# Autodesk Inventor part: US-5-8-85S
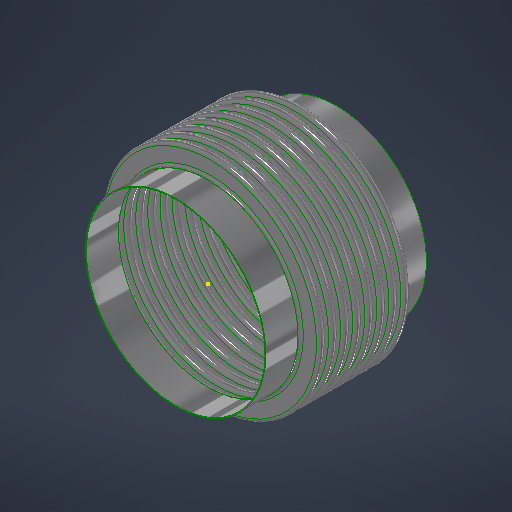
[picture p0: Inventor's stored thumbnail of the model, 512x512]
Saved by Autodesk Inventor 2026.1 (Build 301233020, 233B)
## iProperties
Category: 24 GA (0.024 THICK)
RuleStatus: InUse
Created: 2026-07
Part Number: US-5-8-85S
Project: =STOCK BELLOWS: <Stock Number><SFILL>
Material: ASTM A240-304
Description: =STOCK BELLOWS: <Stock Number>, <SID_> I.D., <SOD_> O.D., <SPLY_> PLY, <Category>, <SNET_CONS> CONS.<PITCH_><STANGENT_> TANGENT<SFILL>
Document SubType Name: Sheet Metal
Designer: LC
Stock Number: U.S-5-8-85S
Surface Area: 659.127 cm^2
Volume: 56.61 cm^3
Sheet Metal Rule: Default
Appearance: STAINLESS STEEL
NET_TUBE: 3.428
COUNTER: 1.500
PBAR: 1.214
PSET: 5.356
PLY: 2
CONS: 2
THK: 0.036
ID: 4.500
OD: 5.500
CONS_: 2
TANGENT: 0.500
PITCH: 0.375
BELLOWS_UPSET: 0.000
NET_CONS: 2
S_CONS: 0
Description_Units: 0
ID_M: 114.30 mm
OD_M: 139.70 mm
THK_M: 0.91 mm
ID_U: 4.500 in
OD_U: 5.500 in
THK_U: 0.036 in
TANGENT2: 0.500
d79: 1.000
d82: 1.000
d83: 26.000
d84: 24.000
d80: 2.571
d81: 10
SID: 2.375
SCONS_: 8
SPITCH: 0.250
SBELLOWS_UPSET: 0.000
SNET_CONS: 8
SS_CONS: 0
SCONS: 8
d174: 8
d177: 0.018
d178: 2.375
d179: 3.000
d180: 0.375
d181: 1.000
d182: 0.000
d190: 8
d191: 1
d192: 1
d193: 8
d194: 0
PART_NUMBER: U.S-5-8-85S
PRESSURE: 85
SIZE: 5.00
STANGENT_: 1.000
d214: 8
d217: 0.030
d218: 6.625
d219: 8.125
d220: 0.500
d221: 1.000
d222: 0.000
d230: 8
d231: 1
d232: 1
d233: 8
d234: 0
STANGENT: 4.000
SPLY_: 1
STHK_: 0.024
SID_: 5.563
SOD_: 6.813
SPITCH_: 0.375
STANGENT__: 1.000
SBELLOWS_UPSET_: 0.000
SDIFF_TAN: 1.000
TAN_TO_TAN: 0.750 in
d252: 2
d275: 2
d287: 0.050
d289: 0.500
d290: 0.000
d263: 2
d265: 1
d268: 2
d269: 0
d286: 2
d288: 1
d291: 2
d292: 0
SOD_NECK: 5 5/8
CFILL: .
SFILL: .
PITCH_: =, <SPITCH_> PITCH,
SREROLL: 0.750
MATTABLE: 20 GA (0.036 THICK)
MESH: ,
CSECT: 2
Author: LC
Keywords: 20 GA (0.036 THICK)
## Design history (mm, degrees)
sketch "Sketch2"
  geometry: L1 (0, -183.595)-(0, 600.956) reference; L2 (58.979, 0)-(57.15, 0); L3 (60.446, -1.467)-(66.554, -1.467); L4 (60.446, -3.296)-(66.554, -3.296); L5 (66.554, -8.058)-(60.446, -8.058); L6 (66.554, -6.229)-(60.446, -6.229); L7 (58.979, -9.525)-(57.15, -9.525); L8 (60.446, 0)-(60.446, -9.525); L9 (66.554, -4.762)-(69.85, -4.763); L10 (57.15, 0)-(57.15, -9.525); L11 (20.376, 102.841)-(20.376, 101.926); L12 (58.262, 488.877)-(58.262, 349.177); L13 (58.262, 479.352)-(58.262, 339.652); L14 (93.133, -58.817)-(93.133, -71.517); L15 (118.746, -66.401)-(118.746, -66.401); L16 (66.554, -6.229)-(66.554, -8.058); L17 (60.446, -6.229)-(60.446, -8.058); L18 (60.446, -7.144)-(66.554, -7.144); L19 (69.85, 0)-(69.85, -9.525); L20 (-66.554, -6.229)-(-66.554, -8.058); L21 (-66.554, -1.467)-(-60.446, -1.467); L22 (-66.554, -3.296)-(-60.446, -3.296); L23 (-60.446, -6.229)-(-66.554, -6.229); L24 (-66.554, -7.144)-(-60.446, -7.144); L25 (-60.446, -8.058)-(-66.554, -8.058); L26 (-60.446, -6.229)-(-60.446, -8.058); L27 (-57.15, -2.522)-(-57.15, -12.047); L28 (-60.446, -4.763)-(-57.15, -4.763); L29 (-66.554, 3.828)-(-66.554, -9.525); L30 (-68.021, 0)-(-69.85, 0); L31 (-69.85, 0)-(-69.85, -9.525); L32 (-68.021, -9.525)-(-69.85, -9.525); A1 r 1.467 centre (60.446, 0) between (58.979, 0) and (60.446, -1.467); A2 r 3.296 centre (60.446, 0) between (57.15, 0) and (60.446, -3.296); A3 r 3.296 centre (66.554, -4.762) between (66.554, -8.058) and (66.554, -1.467); A4 r 1.467 centre (66.554, -4.762) between (66.554, -6.229) and (66.554, -3.296); A5 r 1.467 centre (60.446, -9.525) between (60.446, -8.058) and (58.979, -9.525); A6 r 3.296 centre (60.446, -9.525) between (60.446, -6.229) and (57.15, -9.525); A7 r 2.381 centre (66.554, -4.762) between (66.554, -7.144) and (68.936, -4.762); A8 r 2.381 centre (60.446, -9.525) between (60.446, -7.144) and (58.064, -9.525); A9 r 1.467 centre (-66.554, -9.525) between (-66.554, -8.058) and (-68.021, -9.525); A10 r 1.467 centre (-60.446, -4.763) between (-60.446, -6.229) and (-60.446, -3.296); A11 r 2.381 centre (-60.446, -4.763) between (-60.446, -7.144) and (-58.064, -4.763); A12 r 3.296 centre (-60.446, -4.763) between (-60.446, -8.058) and (-60.446, -1.467); A13 r 2.381 centre (-66.554, -9.525) between (-66.554, -7.144) and (-68.936, -9.525); A14 r 3.296 centre (-66.554, -9.525) between (-66.554, -6.229) and (-69.85, -9.525); A15 r 1.467 centre (-66.554, 0) between (-68.021, 0) and (-66.554, -1.467); A16 r 3.296 centre (-66.554, 0) between (-69.85, 0) and (-66.554, -3.296); 10 further points
  constraints: 62 end point, 38 point on circle, 20 tangent, 16 centre point, 12 parallel, 9 midpoint, 7 vertical, 6 coincident, 6 concentric, 6 point on line, 4 equal radius, 4 perpendicular, 3 horizontal, 1 collinear, 1 horizontal alignment, 10 other
  dimensions: "THK" = 0.9144 distance of L11.start L11.end; "ID" = 114.3 distance of L11.end point (20.376, -12.374); "OD" = 139.7 distance of L12.start L12.end; "PITCH" = 9.525 distance of L12.start L13.start; "TANGENT" = 12.7 distance of L14.start L14.end; "BELLOWS_UPSET" = 0 distance of L15.start L15.end; "d43" = 114.3 diameter of L10 L1 (= ID); "d44" = 139.7 diameter of L9.end L1 (= OD); "d45" = 1.8288 distance between parallel lines of L5 L6 (computed from THK, PLY); "d46" = 3.29565 radius of A3 (computed from PITCH, THK, PLY); "UPSET_PITCH" = 9.525 distance of L2.end L7.end (derived); "SIDEWALL_ANGLE" = 0 deg angle of L3 L9 (derived); "CON_GAP" = 2.9337 distance of point (60.446, -6.229) point (60.446, -3.296) (derived); "TAN1" = 3.74046 dimension on A8 (derived); "TAN2" = 3.74046 dimension on A7 (derived); "LEG1" = 6.1087 distance of L18.start L18.end (derived); "d278" = 1.8288 distance between parallel lines of L25 L23 (derived); "d279" = 3.29565 radius of A12 (derived); "d280" = 9.525 distance of L30.end L31.end (derived); "d281" = 360 deg dimension on L21 L28 (derived); "d282" = 2.9337 distance of point (-66.554, -6.229) point (-66.554, -3.296) (derived); "d283" = 3.74046 dimension on A13 (derived); "d284" = 3.74046 dimension on A11 (derived); "d285" = 6.1087 distance of L24.start L24.end (derived); "d293" = 114.3 diameter of L27 L1 (derived); "d294" = 139.7 diameter of L31 L1 (derived)
  node "Sketch Rectangular Pattern1" dims "d31" = 25.4, "ID" = 114.3
  node "Sketch Rectangular Pattern2" dims "d39" = 25.4, "PITCH" = 9.525
revolve "CONS" stored, may be unused: angle "d48" = 90 deg
node "BELLOW MIDPLANE"
pattern_linear "Rectangular Pattern2" dims "d52" = 9.525 (= UPSET_PITCH)
sketch "Sketch5"
  geometry: C1 r 58.979 at (0, 0) reference; C2 r 57.15 at (0, 0) reference
extrude "TANGENT" new body sketch "Sketch5" distance "d53" = 12.7 (= TANGENT); taper "d54" = 0 deg
revolve "SAMETAN" stored, may be unused: angle "d65" = 90 deg
revolve "DIFFTAN" stored, may be unused: angle "d70" = 90 deg
sketch "Sketch9"
  geometry: L1 (58.391, 0)-(-58.391, 0) reference; L2 (0, -17.78)-(0, 17.78) reference; L3 (41.708, 0)-(-41.708, 0); L4 (41.708, -11.906)-(41.708, 11.906); L5 (29.008, -11.906)-(29.008, 11.906); L6 (15.418, 11.906)-(15.418, -11.906); L7 (-29.008, -11.906)-(-29.008, 11.906); L8 (-41.708, -11.906)-(-41.708, 11.906); L9 (40.914, -11.906)-(40.914, 11.906); L10 (41.708, -11.906)-(40.914, -11.906); L11 (41.708, 11.906)-(40.914, 11.906); L12 (15.815, 11.906)-(15.022, 11.906); L13 (15.022, 11.906)-(15.022, -11.906); L14 (15.022, -11.906)-(15.815, -11.906); L15 (15.815, -11.906)-(15.815, 11.906); L16 (-15.815, 11.906)-(-15.815, -11.906); L17 (-15.418, 11.906)-(-15.418, -11.906); L18 (-15.815, -11.906)-(-15.022, -11.906); L19 (-15.022, -11.906)-(-15.022, 11.906); L20 (-15.022, 11.906)-(-15.815, 11.906); L21 (-41.708, -11.906)-(-40.914, -11.906); L22 (-40.914, -11.906)-(-40.914, 11.906); L23 (-40.914, 11.906)-(-41.708, 11.906); L24 (-41.708, 11.906)-(-41.708, -11.906); L25 (41.708, -0.397)-(-41.708, -0.397); L26 (-41.708, -0.397)-(-41.708, 0.397); L27 (-41.708, 0.397)-(41.708, 0.397); L28 (41.708, 0.397)-(41.708, -0.397); L29 (-41.708, 11.906)-(41.708, 11.906); L30 (41.708, 11.906)-(41.708, 12.7); L31 (41.708, 12.7)-(-41.708, 12.7); L32 (-41.708, 12.7)-(-41.708, 11.906); L33 (41.708, -11.906)-(-41.708, -11.906); L34 (-41.708, -11.906)-(-41.708, -12.7); L35 (-41.708, -12.7)-(41.708, -12.7); L36 (41.708, -12.7)-(41.708, -11.906); 30 further points
  constraints: 68 end point, 13 midpoint, 13 parallel, 8 horizontal, 7 perpendicular, 6 equal length, 3 point on line, 2 vertical, 14 other
  dimensions: "d115" = 23.8125 distance of L4.start L4.end (derived); "d116" = 12.7 distance between parallel lines of L4 L5 (derived); "d117" = 13.58962 distance between parallel lines of L5 L6 (derived); "d125" = 44.42645 distance between parallel lines of L7 L6 (derived); "d127" = 12.7 distance between parallel lines of L8 L7 (derived); "d128" = 26.28962 distance between parallel lines of L6 L4 (derived); "d130" = 83.41607 distance between parallel lines of L8 L4 (derived); "RULER_THK" = 0.79375 distance between parallel lines of L4 L9; "d135" = 0.79375 distance of L13.end L14.end (derived); "d138" = 30.83684 distance of L13.end L16.end (derived); "d143" = 0.79375 distance of L22.end L8.end (derived); "d144" = 0.79375 distance between parallel lines of L27 L25 (derived)
extrude "RULER" join sketch "Sketch9" distance "d149" = 0.79375 (derived); taper "d150" = 0 deg
extrude "BARS" join sketch "Sketch9" distance "d151" = 0.79375 (derived); taper "d152" = 0 deg
pattern_linear "Rectangular Pattern4" dims "d155" = 30.83684 (derived)
sketch "Sketch13"
  geometry: L1 (93.149, -52.467)-(93.149, -77.867); L2 (71.26, 0)-(70.65, 0); L3 (71.26, -9.525)-(70.65, -9.525); L4 (83.839, -7.449)-(73.336, -7.449); L5 (83.839, -6.839)-(73.336, -6.839); L6 (83.839, -4.763)-(86.525, -4.763); L7 (73.336, -2.076)-(83.839, -2.076); L8 (73.336, 0)-(73.336, -9.525); L9 (70.65, 0)-(70.65, -9.525); L10 (58.254, -341.381)-(58.254, -514.431); L11 (58.254, -350.906)-(58.254, -523.956); L12 (58.254, -369.956)-(58.254, -543.006); L13 (58.254, -379.481)-(58.254, -552.531); L14 (58.254, -389.006)-(58.254, -562.056); L15 (58.254, -398.531)-(58.254, -571.581); L16 (58.254, -408.056)-(58.254, -581.106); L17 (58.254, -360.431)-(58.254, -533.481); L18 (20.376, 102.536)-(20.376, 101.926); L19 (73.336, -2.686)-(83.839, -2.686); L20 (0, -696.234)-(0, 235.664) reference; L21 (-23.752, 0)-(142.514, 0) reference; A1 r 2.076 centre (73.336, 0) between (71.26, 0) and (73.336, -2.076); A2 r 2.076 centre (73.336, -9.525) between (73.336, -7.449) and (71.26, -9.525); A3 r 2.686 centre (73.336, -9.525) between (73.336, -6.839) and (70.65, -9.525); A4 r 2.076 centre (83.839, -4.763) between (83.839, -6.839) and (83.839, -2.686); A5 r 2.686 centre (83.839, -4.763) between (83.839, -7.449) and (83.839, -2.076); A6 r 2.686 centre (73.336, 0) between (70.65, 0) and (73.336, -2.686); 6 further points; 1 other entity
  constraints: 38 end point, 15 point on circle, 9 tangent, 6 centre point, 6 parallel, 5 vertical alignment, 4 point on line, 4 vertical, 3 coincident, 3 concentric, 2 collinear, 2 equal radius, 1 horizontal, 1 perpendicular, 23 other
  dimensions: "SBELLOWS_UPSET_" = 0 distance of point (118.762, -66.401) point (118.762, -66.401); "STOTAL_THK_BELLOW__" = 0.6096 distance between parallel lines of L4 L5 (derived); "d224" = 2.68605 radius of A5 (derived); "d225" = 9.525 distance of L2.end L3.end (derived); "SSIDEWALL_ANGLE_" = 0 deg angle of L7 L6 (derived); "SSCON_GAP_" = 4.1529 distance of point (73.336, -6.839) point (73.336, -2.686) (derived); "d235" = 141.3002 diameter of L9 L20 (derived); "d236" = 173.0502 diameter of L6.end L20 (derived)
  node "Sketch Rectangular Pattern4" dims "d228" = 25.4
  node "Sketch Rectangular Pattern5" dims "d229" = 25.4
revolve "SBELLOW" stored, may be unused: angle "d197" = 90 deg
pattern_linear "Rectangular Pattern5" dims "d204" = 9.525 (derived)
revolve "STANGENT" stored, may be unused: angle "d240" = 90 deg
revolve "SSAMETAN" stored, may be unused: angle "d241" = 90 deg
revolve "SDIFFTAN" stored, may be unused: angle "d246" = 90 deg
revolve "INVCON" stored, may be unused: angle "d295" = 90 deg
pattern_linear "Rectangular Pattern6" dims "d298" = 9.525 (derived)
revolve "INVTANGENT" stored, may be unused: angle "d302" = 90 deg
revolve "INVSAMETAN" stored, may be unused: angle "d307" = 90 deg
revolve "INVDIFFTAN" stored, may be unused: angle "d312" = 90 deg
sketch "ID BELLOW MOUNT CALC"
  geometry: L1 (44.45, 0)-(38.1, 0); L2 (38.1, 0)-(38.1, 12.7); L3 (38.1, 12.7)-(44.45, 12.7); L4 (44.45, 12.7)-(44.45, 0); L5 (36.513, 12.7)-(34.684, 12.7); L6 (34.684, 12.7)-(34.684, 0); L7 (34.684, 0)-(36.513, 0); L8 (36.513, 0)-(36.513, 12.7); L9 (0, -2.54)-(0, 15.24) reference; L10 (-8.89, 0)-(53.34, 0) reference; 1 further point
  constraints: 16 end point, 5 parallel, 2 collinear, 2 horizontal, 2 perpendicular
  dimensions: "d314" = 12.7 distance of L5.end L6.end (derived); "d315" = 1.8288 distance of L5.start L5.end (derived); "IG" = 1.5875 distance between parallel lines of L2 L8; "PIPE_OD" = 88.9 diameter of L4 L9; "PIPE_WALL" = 6.35 distance of L2.end L3.end; "ID_MT_BELLOW" = 69.3674 diameter of L6 L9 (derived)
revolve "CFILL" stored, may be unused: angle "d320" = 90 deg
pattern_linear "Rectangular Pattern7" dims "d323" = 9.525 (derived)
revolve "SFILL" stored, may be unused: angle "d324" = 90 deg
pattern_linear "Rectangular Pattern8" dims "d327" = 9.525 (derived)
node "STOCK BELLOW MIDPLANE"
sketch "Sketch21"
  geometry: L1 (0, -100.013)-(0, 100.013) reference; L2 (-100.013, 0)-(100.013, 0) reference; L3 (-0.099, 71.437)-(0.099, 71.437); L4 (0.099, 71.437)-(0.099, 55.562); L5 (0.099, 55.562)-(-0.099, 55.562); L6 (-0.099, 55.562)-(-0.099, 71.437); C1 r 55.562 at (0, 0); C2 r 71.437 at (0, 0); 3 further points
  constraints: 8 end point, 2 centre point, 2 coincident, 2 parallel, 2 tangent, 1 horizontal, 1 perpendicular, 1 other
  dimensions: "d329" = 111.125 diameter of C1 (derived); "d330" = 142.875 diameter of C2 (derived); "d331" = 0.19844 distance of L3.start L3.end
extrude "CLAMSHELL" cut sketch "Sketch21" extent not by distance; stored distance "d332" = 0; taper "d333" = 0 deg
pattern_circular "Circular Pattern1" dims angle "d335" = 180 deg (derived)
node "BELLOW"
sketch "Sketch6"
  geometry: L1 (-19.05, 58.979)-(-6.35, 58.979); L2 (-6.35, 58.979)-(-6.35, 57.15); L3 (-6.35, 57.15)-(-19.05, 57.15); L4 (-19.05, 57.15)-(-19.05, 58.979); L5 (2.54, 0)-(-59.69, 0) reference; L6 (-38.1, -108.388)-(-38.1, 156.601) reference; 1 further point
  constraints: 8 end point, 2 parallel, 1 horizontal, 1 perpendicular
  dimensions: "d61" = 12.7 distance of L2.end L3.end (derived); "d62" = 1.8288 distance of L1.end L2.end (derived); "d63" = 114.3 diameter of L3 L5 (derived); "d64" = 19.05 distance between parallel lines of L4 L6 (derived)
sketch "Sketch12"
  geometry: 1 further point
sketch "Sketch14"
  geometry: L1 (-25.4, 71.26)-(0, 71.26); L2 (0, 71.26)-(0, 70.65); L3 (0, 70.65)-(-25.4, 70.65); L4 (-25.4, 70.65)-(-25.4, 71.26); L5 (5.08, 0)-(-30.48, 0) reference; L6 (0, -11.552)-(0, 69.312) reference; 1 further point
  constraints: 8 end point, 2 parallel, 1 collinear, 1 horizontal, 1 perpendicular
  dimensions: "d237" = 0.6096 distance of L3.end L1.start (derived); "d238" = 141.3002 diameter of L3 L5 (derived); "d239" = 25.4 distance of L1.start L1.end (derived); "SOD_NECK" = 142.5194 diameter of L1 L5 (derived)
sketch "Sketch15"
  geometry: L1 (-11.552, 0)-(69.312, 0) reference; L2 (70.65, -76.2)-(71.26, -76.2); L3 (71.26, -76.2)-(71.26, -101.6); L4 (71.26, -101.6)-(70.65, -101.6); L5 (70.65, -101.6)-(70.65, -76.2); L6 (0, -124.46)-(0, 35.56) reference; 1 further point
  constraints: 8 end point, 2 parallel, 1 horizontal, 1 perpendicular
  dimensions: "d205" = 25.4 distance of L4.end L2.start (derived); "d206" = 0.6096 distance of L3.end L4.end (derived); "d207" = 141.3002 diameter of L5 L6 (derived); "d208" = 76.2 distance between parallel lines of L1 L2 (derived)
node "TANGENT_"
node "SAME_TAN"
sketch "Sketch8"
  geometry: L1 (58.979, -19.05)-(57.15, -19.05); L2 (57.15, -19.05)-(57.15, -31.75); L3 (57.15, -31.75)-(58.979, -31.75); L4 (58.979, -31.75)-(58.979, -19.05); L5 (0, -40.64)-(0, 21.59) reference; L6 (-108.388, 0)-(156.601, 0) reference; 1 further point
  constraints: 8 end point, 2 parallel, 1 horizontal, 1 perpendicular
  dimensions: "d66" = 114.3 diameter of L2 L5 (derived); "TOTAL_THK_BELLOW" = 1.8288 distance of L2.end L3.end (derived); "d68" = 19.05 distance between parallel lines of L1 L6 (derived); "d69" = 12.7 distance of L1.end L2.end (derived)
node "DIFF_TAN"
node "Sketch Rectangular Pattern3" dims "d138" = 30.83684 (derived), "d141" = 25.4
node "SBELLOW_"
node "STANGENT_"
node "SSAME_TAN"
sketch "Sketch16"
  geometry: L1 (71.26, -76.2)-(70.65, -76.2); L2 (70.65, -76.2)-(70.65, -101.6); L3 (70.65, -101.6)-(71.26, -101.6); L4 (71.26, -101.6)-(71.26, -76.2); L5 (0, -124.46)-(0, 35.56) reference; L6 (-11.552, 0)-(69.312, 0) reference; 1 further point
  constraints: 8 end point, 2 parallel, 1 horizontal, 1 perpendicular
  dimensions: "SDIFF_TAN" = 25.4 distance of L3.end L1.start; "d243" = 0.6096 distance of L2.end L3.end (derived); "d244" = 76.2 distance between parallel lines of L1 L6 (derived); "d245" = 141.3002 diameter of L2 L5 (derived)
node "SDIFF_TAN"
body "Solid15"
sketch "Sketch17"
  geometry: L1 (69.85, 12.7)-(68.021, 12.7); L2 (68.021, 12.7)-(68.021, 0); L3 (68.021, 0)-(69.85, 0); L4 (69.85, 0)-(69.85, 12.7); L5 (0, -2.54)-(0, 15.24) reference; L6 (-13.97, 0)-(83.82, 0) reference; 2 further points
  constraints: 8 end point, 2 parallel, 1 horizontal, 1 midpoint, 1 perpendicular, 1 point on line
  dimensions: "INVTANGENT" = 12.7 distance of L3.end L1.start (derived); "d300" = 1.8288 distance of L1.start L1.end (derived); "d301" = 139.7 diameter of L4 L5 (derived)
body "Solid16"
sketch "Sketch18"
  geometry: L1 (69.85, -19.05)-(68.021, -19.05); L2 (68.021, -19.05)-(68.021, -31.75); L3 (68.021, -31.75)-(69.85, -31.75); L4 (69.85, -31.75)-(69.85, -19.05); L5 (-13.97, 0)-(83.82, 0) reference; L6 (0, -40.64)-(0, 21.59) reference; 1 further point
  constraints: 8 end point, 2 parallel, 1 horizontal, 1 perpendicular
  dimensions: "d303" = 19.05 distance between parallel lines of L1 L5 (derived); "d304" = 12.7 distance of L3.end L1.start (derived); "d305" = 1.8288 distance of L2.end L3.end (derived); "d306" = 139.7 diameter of L4 L6 (derived)
body "Solid17"
sketch "Sketch19"
  geometry: L1 (69.85, -19.05)-(68.021, -19.05); L2 (68.021, -19.05)-(68.021, -31.75); L3 (68.021, -31.75)-(69.85, -31.75); L4 (69.85, -31.75)-(69.85, -19.05); L5 (0, -40.64)-(0, 21.59) reference; L6 (-13.97, 0)-(83.82, 0) reference; 1 further point
  constraints: 8 end point, 2 parallel, 1 horizontal, 1 perpendicular
  dimensions: "d308" = 12.7 distance of L1.end L2.end (derived); "d309" = 139.7 diameter of L4 L5 (derived); "d310" = 1.8288 distance of L2.end L3.end (derived); "d311" = 19.05 distance between parallel lines of L1 L6 (derived)
body "Solid18"
body "Solid19"
body "Solid20"
other parameters: "BMPL" = -38.1, "PSET" = 136.0424 (computed from OD, THK, PLY) [user parameter], "PBAR" = 30.83684 (= 0.570796 x PITCH + OD - ID) [user parameter; used in 1 equation term], "COUNTER" = 15 [user parameter], "NET_TUBE" = 87.07367 (computed from CONS_, PBAR, TANGENT) [user parameter], "S_CONS" = 0 [user parameter; used in 1 equation term], "ID_M" = 114.3 (= ID) [user parameter], "OD_M" = 139.7 (= OD) [user parameter], "THK_M" = 0.9144 (= THK) [user parameter], "ID_U" = 114.3 (= ID) [user parameter], "OD_U" = 139.7 (= OD) [user parameter], "THK_U" = 0.9144 (= THK) [user parameter], "D_UNITS" = 0 [user parameter], "TANGENT2" = 12.7 [user parameter], "TAN_TO_TAN" = 19.05 [user parameter], "OD_NECK" = 117.9576 [user parameter], "d79" = 25.4, "d80" = 65.29823 [user parameter], "d82" = 25.4, "d83" = 660.4, "d84" = 609.6, "sa_0" = 4, "FRAME_THK" = 0.79375 [user parameter], "CON_FLAT" = 13.58962 [user parameter], "SID" = 60.325 [user parameter], "SPITCH" = 6.35 [user parameter], "STANGENT_" = 25.4 [user parameter], "SBELLOWS_UPSET" = 0 [user parameter], "SS_CONS" = 0 [user parameter], "STAN_TO_TAN_" = 76.2 [user parameter], "d100" = 0.6096 [user parameter], "d191" = 25.4 [user parameter], "d194" = 0 [user parameter], "STANGENT" = 101.6 [user parameter], "d234" = 0 [user parameter], "SUPSET_PITCH_" = 9.525 [user parameter], "d269" = 0 [user parameter], "d287" = 1.27, "d289" = 12.7, "d290" = 0, "d292" = 0 [user parameter], "Thickness" = 3.048 (derived), "KFactor" = 4.4, "BendRadius" = 3.048 (derived), "BendReliefWidth" = 3.048 (derived), "BendReliefDepth" = 1.524 (derived), "CornerReliefSize" = 12.192 (derived), "SeamGap" = 0.00508, "MinimumRemnant" = 6.096 (derived), "TransitionRadius" = 3.048 (derived), "JacobiRadiusSize" = 3.048 (derived), "GapSize" = 3.048 (derived), "SREROLL" = 19.05 [user parameter], "CUR_STK_PITCH" = 9.525 [user parameter], "d328" = -38.1 (derived), "CSECTDEG" = 180 deg [user parameter]
